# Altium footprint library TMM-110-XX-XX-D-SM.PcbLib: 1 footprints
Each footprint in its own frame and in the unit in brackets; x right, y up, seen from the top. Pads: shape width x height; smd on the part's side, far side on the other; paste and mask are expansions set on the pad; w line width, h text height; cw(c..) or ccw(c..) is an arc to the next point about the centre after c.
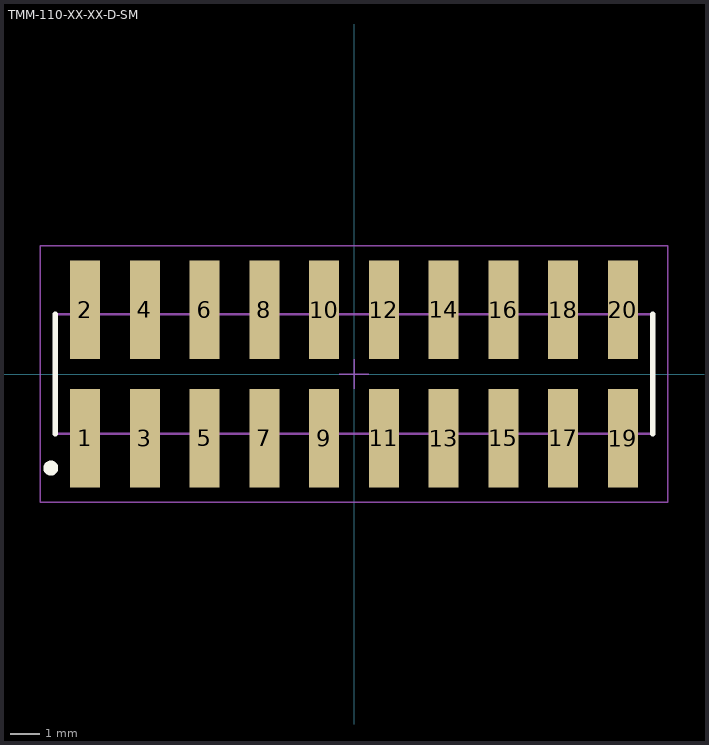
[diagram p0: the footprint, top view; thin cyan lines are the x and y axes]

## TMM-110-XX-XX-D-SM [mm] "2.00mm pitch, 20 pin, terminal strip; double row, SMT"
height 2.77
pads (20):
  rect 1x3.3 smd mask+0: 1(-9,-2.15) 2(-9,2.15) 3(-7,-2.15) 4(-7,2.15) 5(-5,-2.15) 6(-5,2.15) 7(-3,-2.15) 8(-3,2.15) 9(-1,-2.15) 10(-1,2.15) 11(1,-2.15) 12(1,2.15) 13(3,-2.15) 14(3,2.15) 15(5,-2.15) 16(5,2.15) 17(7,-2.15) 18(7,2.15) 19(9,-2.15) 20(9,2.15)
Top Overlay:
  circle w0.25: c-10.15,-3.15 r0.125
  lines w0.2: -10,-2 -10,2 ; 10,-2 10,2
Mechanical 12:
  lines w0.001: -10,-2 -10,2 10,2 10,-2 -10,-2
Mechanical 13:
  lines w0.1: -10,-2 -10,2 10,2 10,-2 -10,-2
  text ".Designator" at 0,-0.127 h1.52
Mechanical 15:
  lines w0.05: -0.5,0 0.5,0 ; 0,-0.5 0,0.5 ; -10.5,-4.3 -10.5,4.3 10.5,4.3 10.5,-4.3 -10.5,-4.3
